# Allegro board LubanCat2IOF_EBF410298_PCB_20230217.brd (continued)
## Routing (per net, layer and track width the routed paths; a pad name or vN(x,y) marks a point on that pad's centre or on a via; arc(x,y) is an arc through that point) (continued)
SATA0TXN: length 3.1
  BOTTOM w0.114: C61.2 122.26,9.97 arc(122.14,9.79) 122.1,9.57 122.1,8.2 arc(122.14,7.98) 122.26,7.8 J34.3
SATA0TXP: length 3.1
  BOTTOM w0.114: C60.2 121.69,10.02 arc(121.81,9.83) 121.85,9.61 121.85,8.2 arc(121.81,7.98) 121.69,7.8 J34.2
SATA_5V: length 12.8
  TOP w0.305: C206.2 R201.2 118.62,18.36 119.23,17.75 v1(124.33,17.75)
  BOTTOM w0.305: v1(124.33,21.89) C208.1 123.44,21.86
  BOTTOM w0.508: J1.1 122.5,16 ; J1.1 121.6,15.1 ; J1.1 121.6,16.9 ; J1.1 120.7,16
  vias: v1(124.33,20.89) v1(124.33,19.89) v1(125.33,21.89) v1(125.33,20.89) v1(125.33,19.89)
SATA_12V: length 4.8
  TOP w0.305: C59.1 v1(135.76,16.3)
  BOTTOM w0.508: J1.4 129.22,16.9 ; J1.4 128.32,16 ; J1.4 130.12,16 ; J1.4 129.22,15.1
  vias: v1(135.76,15.3) v1(136.76,16.3) v1(136.76,15.3)
SATA_PWR_EN: length 143
  TOP w0.173: v1(132.68,6.27) 131.78,7.17 131.78,18.57 131.43,18.92 122.11,18.92 v1(121.41,19.61) R209.2 ; J38.119 v1(44.1,31.92)
  BOTTOM w0.173: v1(44.1,31.92) 106.65,31.92 113.54,25.04 115.37,25.04 115.77,24.63 115.77,20.32 116.18,19.91 121.12,19.91 v1(121.41,19.61) ; R206.1 134.87,6.9 133.32,6.9 v1(132.68,6.27)
SDMMC0_CLK: length 135.7
  TOP w0.173: J38.95 v1(38.1,34)
  BOTTOM w0.173: v1(38.1,34) 108.98,34 110.19,32.78 117.04,32.78 117.29,32.53 117.29,31.69 117.46,31.52 117.88,31.52 118.14,31.77 118.14,32.46 118.39,32.71 118.75,32.71 119,32.46 119,31.77 119.25,31.52 128.78,31.52 135.1,25.19 138.62,25.19 R54.1
SDMMC0_CMD: length 136.9
  TOP w0.173: J38.97 38.6,33.93 v1(39.59,32.93)
  BOTTOM w0.173: v1(39.59,32.93) 40.14,33.48 108.3,33.48 109.6,32.18 114.38,32.18 114.64,31.93 114.64,31.21 114.89,30.96 115.25,30.96 115.51,31.21 115.51,31.87 115.76,32.13 116.12,32.13 116.37,31.87 116.37,31.21 116.62,30.96 128.6,30.96 136.03,23.54 136.03,22.9 136.51,22.41 R53.1
SDMMC0_D0: length 136.9
  TOP w0.173: J38.99 39.1,35.01 v1(39.59,34.51)
  BOTTOM w0.173: R57.1 134.32,26.81 129.08,32.05 125.28,32.05 125.03,32.3 125.03,32.97 124.78,33.22 124.42,33.22 124.17,32.97 124.17,32.3 123.92,32.05 123.58,32.05 123.33,32.3 123.33,33.05 123.08,33.3 122.72,33.3 122.47,33.05 122.47,32.3 122.21,32.05 121.85,32.05 121.6,32.3 121.6,33.05 121.35,33.3 120.99,33.3 120.74,33.05 120.74,32.3 120.49,32.05 120.13,32.05 119.87,32.3 119.87,33.05 119.62,33.3 110.77,33.3 109.56,34.51 v1(39.59,34.51)
SDMMC0_D1: length 135.8
  TOP w0.173: J38.105 40.6,35.77 v1(40.64,35.73)
  BOTTOM w0.173: v1(40.64,35.73) 109.07,35.73 110.99,33.82 125.6,33.82 125.85,33.57 125.85,32.86 126.11,32.61 126.41,32.61 126.66,32.86 126.66,33.5 126.91,33.75 127.27,33.75 127.52,33.5 127.52,32.86 127.78,32.61 129.44,32.61 134.13,27.92 135.36,27.92 135.61,28.17 135.61,29.26 135.87,29.51 136.23,29.51 136.48,29.26 136.48,28.17 136.73,27.92 137.09,27.92 137.34,28.17 137.34,29.26 137.6,29.51 137.95,29.51 138.21,29.26 138.21,28.17 138.46,27.92 R60.1
SDMMC0_D2: length 136.8
  TOP w0.173: J38.93 37.6,33.43 v1(38.1,32.93)
  BOTTOM w0.173: R51.1 136.7,20.22 134.87,22.04 134.87,23.22 128.08,30.02 109.88,30.02 107.46,32.44 38.59,32.44 v1(38.1,32.93)
SDMMC0_D3: length 136.9
  TOP w0.173: v1(40.64,32.94) 40.1,33.48 J38.103
  BOTTOM w0.173: v1(40.64,32.94) 40.66,32.96 107.78,32.96 110.26,30.48 110.87,30.48 111.12,30.73 111.12,31.34 111.37,31.59 111.73,31.59 111.99,31.34 111.99,30.73 112.24,30.48 112.6,30.48 112.85,30.73 112.85,31.34 113.1,31.59 113.46,31.59 113.71,31.34 113.71,30.73 113.97,30.48 128.35,30.48 135.51,23.32 135.51,22.45 136.64,21.32 R52.1
SDMMC0_DET: length 128.9
  TOP w0.173: J38.101 39.6,37.14 v1(39.59,37.13)
  BOTTOM w0.173: R61.1 139.2,29.99 138.81,30.37 132.61,30.37 128.65,34.34 111.82,34.34 109.15,37 39.72,37 v1(39.59,37.13)
SIM_CLK0: length 39.4
  TOP w0.173: J35.12 v1(124.3,65.68)
  ART03 w0.16: v1(136.02,39.8) 135.38,40.43 135.38,51.99 134.75,52.62 128.27,52.62 127.64,53.26 127.64,62.55 127.31,62.87 125.01,62.87 124.79,63.09 124.79,65.19 v1(124.3,65.68)
  BOTTOM w0.173: R20.1 v1(136.02,39.8)
SIM_DATA0: length 44.2
  TOP w0.173: J35.10 125.1,66.88 v1(125.3,66.68)
  ART03 w0.16: v1(138.52,36.24) 138.01,36.75 137.04,36.75 136.5,37.29 136.5,52.77 136.02,53.26 128.78,53.26 128.14,53.89 128.14,63.29 127.89,63.55 126.11,63.55 125.79,63.87 125.79,66.19 v1(125.3,66.68)
  BOTTOM w0.173: R21.1 v1(138.52,36.24)
SIM_RST0: length 43.4
  TOP w0.173: J35.14 123.5,66.85 123.33,66.68 v1(122.86,66.68)
  ART03 w0.16: v1(122.86,66.68) 123.44,66.09 123.44,62.53 123.7,62.28 126.68,62.28 127,61.96 127,52.62 127.64,51.99 133.99,51.99 134.75,51.23 134.75,38.53 v1(136.02,37.26)
  BOTTOM w0.173: R19.1 v1(136.02,37.26)
SIM_VDD: length 47.7
  TOP w0.305: J35.8 125.9,67.08 v1(126.3,66.68)
  ART03 w0.305: v1(126.3,66.68) 128.91,64.07 128.91,54.63 129.51,54.02 136.4,54.02 137.62,52.8 137.62,40.92 138.23,40.32 v1(140.2,40.32) 140.2,37.87 139.59,37.26 v1(138.52,37.26)
  BOTTOM w0.305: R18.1 v1(138.52,37.26) ; U14.1 140.2,40.31 v1(140.2,40.32) U15.6
SPKN_OUT: length 18.5
  TOP w0.254: J38.30 21.85,74.39 22.29,74.82 34.18,74.82 34.47,74.54 34.47,74.02 v1(34.16,73.72)
  BOTTOM w0.254: R218.1 v1(34.16,73.72)
SPKP_OUT: length 20
  TOP w0.254: J38.28 21.35,74.6 21.99,75.23 34.35,75.23 34.87,74.71 34.87,74.02 v1(35.18,73.72)
  BOTTOM w0.254: R217.1 v1(35.18,73.72)
U7_RX: length 7.6
  TOP w0.173: J9.3 94.25,7.12 93.9,6.78 J13.5
U7_TX: length 9.2
  TOP w0.173: J13.6 89.08,10 95.9,10 96.25,9.66 J9.2
U9_RX: length 7.5
  TOP w0.173: J14.5 93.9,12.75 94.25,13.09 J12.3
U9_TX: length 8.6
  TOP w0.173: 88.39,15.29 88.95,15.85 95.02,15.85 J12.2
UART2_RX: length 13.2
  TOP w0.173: U12.2 2.42,21.68 2.59,21.51 4.4,21.51 4.57,21.34 4.57,17.62 4.74,17.45 v1(6.6,17.45)
  BOTTOM w0.173: R36.2 v1(6.6,17.45)
UART2_RX_M0_DEBUG: length 101.8
  TOP w0.173: J38.193 64.1,58.41 v1(63.6,57.91) ; U12.4 v1(1.77,23.04)
  ART03 w0.16: v1(63.6,57.91) 63.09,58.42 48.59,58.42 47.57,57.4 36.6,57.4 v1(36.1,56.91)
  BOTTOM w0.173: v1(1.77,23.04) 12.45,23.04 12.93,23.52 12.93,35.47 14.69,37.23 22.96,37.23 23.67,37.95 23.67,40.9 22.56,42.02 22.56,55.87 23.59,56.91 v1(36.1,56.91)
UART2_TX: length 5.1
  TOP w0.173: U4.4 5.96,20.76 v1(6.6,20.11)
  BOTTOM w0.173: R23.2 v1(6.6,20.11)
UART2_TX_M0_DEBUG: length 91.5
  TOP w0.173: J38.191 v1(63.6,60.91) ; U4.2 6.61,27.57 v1(7.26,28.22)
  ART03 w0.16: v1(63.6,60.91) 64.14,60.37 64.14,59.73 63.81,59.41 47.73,59.41 46.74,58.42 36.61,58.42 v1(36.1,57.91)
  BOTTOM w0.173: v1(7.26,28.22) 11.94,28.22 12.29,28.57 12.29,35.73 14.43,37.87 22.69,37.87 23.04,38.21 23.04,40.64 21.92,41.75 21.92,56.13 23.7,57.91 v1(36.1,57.91)
UART3_RX_M1: length 82.1
  TOP w0.173: v1(46.1,56.91) 46.1,27.18 46.79,26.49 53.63,26.49 53.98,26.14 U8.1 ; J38.271 v1(83.6,63.93)
  BOTTOM w0.173: v1(46.1,56.91) 46.57,56.43 66.02,56.43 72.11,62.53 82.2,62.53 v1(83.6,63.93)
UART3_TX_M1: length 70
  TOP w0.173: U8.4 v1(50.16,25.95) ; v1(83.59,53.95) 83.59,54 83.1,54.49 J38.269
  ART03 w0.16: v1(50.16,25.95) 50.83,25.29 75.95,25.29 76.94,26.28 76.94,50.47 78.16,51.69 79.45,51.69 79.91,52.14 81.79,52.14 v1(83.59,53.95)
UART4_RX_M1: length 75.3
  TOP w0.173: v1(46.12,57.89) 46.1,57.89 46.1,57.91 45.61,57.41 45.61,26.8 46.35,26.06 U13.1 ; J38.267 v1(82.6,63.93)
  BOTTOM w0.173: v1(82.6,63.93) 81.63,62.96 71.93,62.96 65.91,56.94 58.62,56.94 57.86,57.7 46.3,57.7 v1(46.12,57.89)
UART4_TX_M1: length 75.7
  TOP w0.173: U13.4 v1(42.55,25.95) ; J38.265 82.1,54.44 v1(82.59,53.95)
  ART03 w0.16: v1(42.55,25.95) 43.13,26.54 75.83,26.54 76.38,27.09 76.38,50.54 79.78,53.95 v1(82.59,53.95)
UART7_RX: length 18.1
  TOP w0.173: J13.3 84.38,8.25 84.38,17.36 D9.1 83.33,19.71 83.33,22.39 R50.2
UART7_RX_M1: length 72.8
  TOP w0.173: J38.283 86.6,58.63 88.74,56.48 99.65,56.48 101.35,54.79 v1(101.35,40.5) ; R50.1 v1(82.68,24.82)
  ART03 w0.16: v1(101.35,40.5) 102.06,39.78 102.06,31.9 101.55,31.39 88.5,31.39 88.34,31.23 88.34,23.9 87.66,23.21 83.01,23.21 82.68,23.54 v1(82.68,24.82)
UART7_TX: length 15
  TOP w0.173: J13.4 84.86,10.31 84.86,18.4 D8.1 84.86,19.72 84.86,22.38 R49.2
UART7_TX_M1: length 68.3
  TOP w0.173: R49.1 v1(84.2,24.82) ; v1(101.35,39.5) 100.84,40 100.84,54.59 99.32,56.1 88.41,56.1 86.1,58.42 J38.281
  ART03 w0.16: v1(84.2,24.82) 84.2,32.59 84.52,32.91 99.12,32.91 99.44,33.23 99.44,39.54 99.88,39.98 100.86,39.98 v1(101.35,39.5)
UART9_RX: length 11.5
  TOP w0.173: R44.2 88.04,22.25 88.04,19.85 D7.1 87.25,14.14 J14.3
UART9_RX_M1: length 72.1
  TOP w0.173: J38.279 85.6,58.01 87.91,55.7 98.93,55.7 100.35,54.29 v1(100.35,40.5) ; R44.1 v1(87.25,24.82)
  ART03 w0.16: v1(100.35,40.5) 98.92,40.5 98.6,40.18 98.6,33.85 98.27,33.52 83.87,33.52 83.47,33.12 83.47,24.2 83.69,23.97 86.41,23.97 v1(87.25,24.82)
UART9_TX: length 8.3
  TOP w0.173: 85.85,15.29 85.72,15.41 D6.1 86.38,19.71 86.38,22.39 R43.2
UART9_TX_M1: length 65.5
  TOP w0.173: R43.1 v1(85.72,24.82) ; v1(100.35,39.5) 99.69,40.15 99.69,53.74 98.96,54.48 87.7,54.48 87.35,54.82 87.35,55.57 85.1,57.82 J38.277
  ART03 w0.16: v1(100.35,39.5) 100.35,32.52 100.03,32.2 86.2,32.2 85.72,31.73 v1(85.72,24.82)
USB2_HOST2_DM: length 44.6
  TOP w0.132: R152.2 v1(126.75,78.63) ; J38.304 92.35,71.43 arc(92.34,71.5) 92.29,71.56 92.28,71.58 arc(92.23,71.64) 92.22,71.72 92.22,71.88 arc(92.24,72) 92.31,72.1 92.59,72.38 arc(92.73,72.47) 92.89,72.5 93.45,72.5 arc(93.56,72.46) 93.6,72.36 arc(93.64,72.25) 93.75,72.21 93.98,72.21 arc(94.09,72.25) 94.13,72.36 arc(94.17,72.46) 94.28,72.5 94.51,72.5 arc(94.61,72.46) 94.66,72.36 arc(94.7,72.25) 94.81,72.21 95.04,72.21 arc(95.14,72.25) 95.19,72.36 arc(95.23,72.46) 95.33,72.5 95.57,72.5 arc(95.67,72.46) 95.71,72.36 arc(95.76,72.25) 95.86,72.21 96.09,72.21 arc(96.2,72.25) 96.24,72.36 arc(96.29,72.46) 96.39,72.5 96.62,72.5 arc(96.73,72.46) 96.77,72.36 arc(96.81,72.25) 96.92,72.21 97.15,72.21 arc(97.26,72.25) 97.3,72.36 arc(97.34,72.46) 97.45,72.5 98.24,72.5 arc(98.5,72.55) 98.71,72.7 98.91,72.9 arc(99.05,72.99) 99.21,73.02 101.43,73.02 arc(101.61,72.94) 101.69,72.75 101.69,72.59 arc(101.65,72.4) 101.55,72.23 v1(101.38,72.07)
  BOTTOM w0.132: v1(101.38,72.07) 101.65,72.34 arc(101.68,72.38) 101.69,72.44 101.69,72.57 arc(102.94,75.57) 105.94,76.82 126.05,76.82 arc(126.82,77.13) 127.13,77.9 127.13,77.98 arc(127.09,78.23) 126.95,78.43 v1(126.75,78.63)
USB2_HOST2_DP: length 44
  TOP w0.132: v1(102.24,72.07) 102.08,72.23 arc(101.97,72.4) 101.93,72.59 101.93,72.75 arc(101.78,73.11) 101.43,73.26 99.21,73.26 arc(98.95,73.21) 98.74,73.06 98.54,72.87 arc(98.41,72.78) 98.24,72.74 92.89,72.74 arc(92.64,72.69) 92.42,72.55 92.14,72.27 arc(92.02,72.09) 91.98,71.88 91.98,71.72 arc(91.97,71.64) 91.92,71.58 91.91,71.56 arc(91.86,71.5) 91.85,71.43 J38.302 ; R153.2 v1(127.76,78.63)
  BOTTOM w0.132: v1(102.24,72.07) 101.97,72.34 arc(101.94,72.38) 101.93,72.44 101.93,72.57 arc(103.1,75.4) 105.94,76.58 126.05,76.58 arc(126.99,76.96) 127.37,77.9 127.37,77.98 arc(127.42,78.23) 127.56,78.43 v1(127.76,78.63)
USB2_HOST3_DM: length 40.3
  TOP w0.132: J38.298 90.85,71.43 arc(90.84,71.5) 90.79,71.56 90.78,71.58 arc(90.73,71.64) 90.72,71.72 90.72,72.64 arc(91,73.3) 91.66,73.58 97.73,73.58 arc(97.98,73.63) 98.19,73.77 99.87,75.45 arc(100.01,75.66) 100.06,75.91 100.06,79.86 arc(100.01,80.12) 99.87,80.33 98.04,82.16 arc(97.95,82.29) 97.92,82.45 97.92,83.37 arc(97.95,83.44) 98.02,83.47 arc(98.09,83.5) 98.12,83.57 98.12,83.9 arc(98.09,83.97) 98.02,84 arc(97.95,84.03) 97.92,84.1 97.92,84.43 arc(97.95,84.5) 98.02,84.53 arc(98.09,84.56) 98.12,84.63 98.12,84.95 arc(98.09,85.03) 98.02,85.06 arc(97.95,85.09) 97.92,85.16 97.92,92.24 arc(97.95,92.43) 98.06,92.59 v1(98.23,92.76)
  BOTTOM w0.132: v1(98.23,92.76) 98.06,92.92 arc(97.95,93.08) 97.92,93.27 97.92,93.34 arc(97.95,93.51) 98.04,93.64 98.32,93.92 arc(98.45,94.01) 98.62,94.04 104.73,94.04 arc(104.8,94.03) 104.87,93.99 104.88,93.97 arc(104.95,93.93) 105.02,93.91 U28.14
USB2_HOST3_DP: length 40.2
  TOP w0.132: v1(97.37,92.76) 97.53,92.59 arc(97.64,92.43) 97.68,92.24 97.68,82.45 arc(97.73,82.2) 97.87,81.99 99.7,80.16 arc(99.79,80.02) 99.82,79.86 99.82,75.91 arc(99.79,75.75) 99.7,75.62 98.03,73.94 arc(97.89,73.85) 97.73,73.82 91.66,73.82 arc(90.83,73.47) 90.48,72.64 90.48,71.72 arc(90.47,71.64) 90.42,71.58 90.41,71.56 arc(90.36,71.5) 90.35,71.43 J38.296
  BOTTOM w0.132: U28.15 105.02,94.41 arc(104.95,94.4) 104.88,94.36 104.87,94.34 arc(104.8,94.3) 104.73,94.28 98.62,94.28 arc(98.36,94.23) 98.15,94.09 97.87,93.81 arc(97.73,93.6) 97.68,93.34 97.68,93.27 arc(97.64,93.08) 97.53,92.92 v1(97.37,92.76)
USB3_HOST1_DM: length 97.6
  TOP w0.132: v1(46.03,73.42) 45.87,73.25 arc(45.76,73.09) 45.72,72.9 45.72,71.72 arc(45.73,71.64) 45.78,71.58 45.79,71.56 arc(45.84,71.5) 45.85,71.43 J38.126 ; R148.2 v1(124.71,78.63)
  BOTTOM w0.132: v1(124.71,78.63) 124.92,78.43 arc(125.05,78.23) 125.1,77.98 arc(125,77.74) 124.76,77.64 124.36,77.64 arc(124.29,77.67) 124.26,77.75 arc(124.23,77.82) 124.16,77.85 123.84,77.85 arc(123.76,77.82) 123.73,77.75 arc(123.7,77.67) 123.63,77.64 105.08,77.64 arc(103.06,77.24) 101.33,76.09 100.39,75.15 arc(99.08,74.27) 97.53,73.96 73.48,73.96 arc(72.44,73.75) 71.56,73.17 68.82,70.42 arc(68.67,70.2) 68.62,69.95 68.62,69.74 arc(68.5,69.12) 68.15,68.6 65,65.45 arc(63.66,64.56) 62.08,64.24 49.74,64.24 arc(46.9,65.42) 45.72,68.27 45.72,73.05 arc(45.73,73.1) 45.76,73.14 v1(46.03,73.42)
USB3_HOST1_DP: length 98.1
  TOP w0.132: J38.124 45.35,71.43 arc(45.36,71.5) 45.41,71.56 45.42,71.58 arc(45.47,71.64) 45.48,71.72 45.48,72.9 arc(45.44,73.09) 45.33,73.25 v1(45.17,73.42) ; R149.2 v1(125.73,78.63)
  BOTTOM w0.132: v1(125.73,78.63) 125.53,78.43 arc(125.39,78.23) 125.34,77.98 arc(125.17,77.57) 124.76,77.41 105.08,77.41 arc(103.15,77.02) 101.5,75.92 100.56,74.98 arc(99.17,74.05) 97.53,73.72 73.48,73.72 arc(72.53,73.53) 71.73,73 68.99,70.25 arc(68.89,70.11) 68.86,69.95 68.86,69.74 arc(68.72,69.03) 68.32,68.43 65.17,65.29 arc(63.75,64.34) 62.08,64 49.74,64 arc(46.73,65.25) 45.48,68.27 45.48,73.05 arc(45.47,73.1) 45.44,73.14 v1(45.17,73.42)
USB3_HOST1_SSRXN: length 96.3
  TOP w0.132: J38.130 46.85,71.43 arc(46.86,71.5) 46.91,71.56 46.92,71.58 arc(46.97,71.64) 46.98,71.72 46.98,72.53 arc(46.96,72.61) 46.92,72.68 46.85,72.75 arc(46.75,72.9) 46.72,73.07 46.72,74.24 arc(46.68,74.43) 46.57,74.59 v1(46.41,74.76) ; R150.2 v1(122.68,78.63)
  BOTTOM w0.132: v1(46.41,74.76) 46.68,74.48 arc(46.83,74.27) 46.88,74.01 46.88,71.63 arc(46.85,71.56) 46.78,71.53 arc(46.71,71.51) 46.69,71.44 46.69,71.1 arc(46.71,71.03) 46.78,71.01 arc(46.85,70.98) 46.88,70.91 46.88,70.57 arc(46.85,70.51) 46.78,70.48 arc(46.71,70.45) 46.69,70.38 46.69,70.05 arc(46.71,69.98) 46.78,69.95 arc(46.85,69.92) 46.88,69.85 46.88,68.47 arc(47.9,66.01) 50.36,64.99 61.51,64.99 arc(63.11,65.31) 64.47,66.22 67.34,69.08 arc(67.64,69.53) 67.74,70.07 67.74,70.35 arc(67.85,70.89) 68.15,71.35 71.62,74.82 arc(71.99,75.07) 72.44,75.15 93.53,75.15 arc(93.78,75.21) 94,75.35 94.89,76.24 arc(95.02,76.33) 95.19,76.36 96.6,76.36 arc(96.85,76.41) 97.07,76.56 97.94,77.43 arc(98.08,77.53) 98.24,77.56 99.31,77.56 arc(99.56,77.61) 99.78,77.75 100.32,78.3 arc(100.46,78.39) 100.62,78.42 120.48,78.42 arc(120.73,78.47) 120.94,78.61 121.05,78.72 arc(121.26,78.86) 121.52,78.91 122.22,78.91 arc(122.39,78.88) 122.53,78.78 v1(122.68,78.63)
USB3_HOST1_SSRXP: length 96.5
  TOP w0.132: v1(47.27,74.76) 47.1,74.59 arc(46.99,74.43) 46.96,74.24 46.96,73.07 arc(46.97,72.99) 47.02,72.92 47.09,72.85 arc(47.19,72.7) 47.22,72.53 47.22,71.72 arc(47.23,71.64) 47.28,71.58 47.29,71.56 arc(47.34,71.5) 47.35,71.43 J38.132 ; R151.2 v1(123.7,78.63)
  BOTTOM w0.132: v1(123.7,78.63) 123.57,78.63 arc(123.48,78.65) 123.4,78.71 123.13,78.97 arc(122.92,79.12) 122.66,79.17 121.43,79.17 arc(121.18,79.12) 120.96,78.97 120.77,78.78 arc(120.64,78.69) 120.48,78.66 100.62,78.66 arc(100.37,78.61) 100.15,78.47 99.61,77.92 arc(99.47,77.83) 99.31,77.8 98.24,77.8 arc(97.99,77.75) 97.77,77.6 96.9,76.73 arc(96.76,76.63) 96.6,76.6 95.19,76.6 arc(94.93,76.55) 94.72,76.41 93.83,75.52 arc(93.69,75.43) 93.53,75.39 72.44,75.39 arc(71.9,75.29) 71.45,74.98 67.99,71.52 arc(67.63,70.99) 67.5,70.35 67.5,70.07 arc(67.42,69.63) 67.17,69.25 64.31,66.39 arc(63.02,65.53) 61.51,65.23 50.36,65.23 arc(48.07,66.18) 47.12,68.47 47.12,74.5 arc(47.14,74.6) 47.19,74.69 v1(47.27,74.76)
USB3_HOST1_SSTXN: length 99.7
  TOP w0.132: C142.2 v1(128.78,78.63) ; J38.134 47.85,71.43 arc(47.86,71.5) 47.91,71.56 47.92,71.58 arc(47.97,71.64) 47.98,71.72 47.98,72.9 arc(47.94,73.09) 47.83,73.25 v1(47.67,73.42)
  BOTTOM w0.132: v1(47.67,73.42) 47.88,73.21 arc(48.02,72.99) 48.07,72.74 48.07,68.82 arc(48.83,66.99) 50.66,66.23 62,66.23 arc(62.61,66.35) 63.13,66.7 65.1,68.67 arc(65.7,69.57) 65.91,70.63 65.91,71.14 arc(65.96,71.38) 66.09,71.58 69.67,75.16 arc(71.11,76.11) 72.8,76.45 92.59,76.45 arc(92.84,76.5) 93.06,76.64 95.12,78.7 arc(95.25,78.8) 95.41,78.83 97.17,78.83 arc(97.36,78.87) 97.52,78.97 98.26,79.72 arc(98.46,79.85) 98.69,79.89 113.42,79.89 arc(113.63,79.85) 113.81,79.73 113.89,79.65 arc(114.08,79.52) 114.31,79.48 119.42,79.48 arc(119.67,79.53) 119.89,79.67 120.42,80.2 arc(120.55,80.29) 120.72,80.33 128.74,80.33 arc(129.04,80.2) 129.17,79.9 129.17,79.08 arc(129.16,79.03) 129.13,78.98 v1(128.78,78.63)
USB3_HOST1_SSTXP: length 99.6
  TOP w0.132: v1(48.53,73.42) 48.37,73.25 arc(48.26,73.09) 48.22,72.9 48.22,71.72 arc(48.23,71.64) 48.28,71.58 48.29,71.56 arc(48.34,71.5) 48.35,71.43 J38.136 ; C143.2 v1(129.79,78.63)
  BOTTOM w0.132: v1(48.53,73.42) 48.41,73.3 arc(48.34,73.19) 48.31,73.05 48.31,68.82 arc(49,67.16) 50.66,66.47 62,66.47 arc(62.52,66.57) 62.96,66.87 64.94,68.84 arc(65.48,69.66) 65.67,70.63 65.67,71.14 arc(65.74,71.47) 65.92,71.74 69.51,75.33 arc(71.02,76.33) 72.8,76.69 92.59,76.69 arc(92.75,76.72) 92.89,76.81 94.95,78.87 arc(95.16,79.02) 95.41,79.07 97.17,79.07 arc(97.27,79.09) 97.35,79.14 98.09,79.88 arc(98.37,80.07) 98.69,80.13 113.42,80.13 arc(113.72,80.07) 113.98,79.9 114.06,79.82 arc(114.18,79.74) 114.31,79.72 119.42,79.72 arc(119.58,79.75) 119.72,79.84 120.25,80.37 arc(120.46,80.51) 120.72,80.56 128.74,80.56 arc(129.21,80.37) 129.41,79.9 129.41,79.08 arc(129.42,79.03) 129.44,78.98 v1(129.79,78.63)
USB3_OTG0_DM: length 41.9
  TOP w0.132: 27.44,90.15 27.31,90.02 25.06,90.02 24.42,90.66 24.42,91.74 24.55,91.87 J36.B7 24.55,94.88 24.39,95.03 23.74,95.03 23.55,94.85 J36.A7 ; 27.44,90.15 D26.1 ; 27.44,90.15 27.63,89.96 29.13,89.96 29.97,89.12 29.97,82.95 31.04,81.89 39.37,81.89 40.22,81.04 40.22,71.64 40.35,71.51 J38.104
USB3_OTG0_DP: length 41.9
  TOP w0.132: 27.44,89.59 27.57,89.72 29.03,89.72 29.73,89.03 29.73,82.85 30.94,81.65 39.27,81.65 39.98,80.94 39.98,71.64 39.85,71.51 J38.102 ; 27.44,89.59 27.44,89.65 27.31,89.78 24.97,89.78 24.18,90.57 24.18,91.74 24.05,91.87 J36.A6 v1(24.05,94.36) ; 27.44,89.59 D25.1 ; J36.B6 v1(23.05,94.36)
  BOTTOM w0.132: v1(23.05,94.36) 23.05,93.87 23.18,93.74 23.92,93.74 24.05,93.87 v1(24.05,94.36)
USB3_OTG0_ID: length 42.9
  TOP w0.173: J38.118 43.85,71.96 43.5,72.31 41.33,72.31 40.98,72.66 40.98,81.77 39.95,82.8 32,82.8 31.63,83.18 31.63,96.03 31.09,96.57 27.52,96.57 v1(26.76,97.32)
  BOTTOM w0.173: R160.2 v1(26.76,97.32)
USB3_OTG0_VBUSDET: length 40.6
  TOP w0.173: R158.2 v1(23.61,89.25) 23.61,88.98 23.96,88.63 26.63,88.63 26.97,88.29 26.97,80.55 27.32,80.2 v1(39.05,80.2) ; J38.120 44.35,74.3 44,74.65 41.98,74.65 41.63,74.99 41.63,79.84 v1(41.99,80.2)
  BOTTOM w0.173: v1(41.99,80.2) v1(39.05,80.2) ; R158.2 v1(23.61,89.25)
USB20_DM1: length 11
  TOP w0.132: J19.11 126.6,87.18 126.47,87.31 126.47,87.5 arc(126.48,87.57) 126.52,87.63 126.74,87.85 arc(126.88,87.94) 127.04,87.97 127.82,87.97 arc(128.02,87.89) 128.11,87.68 128.11,87.04 arc(128.08,86.89) 127.99,86.76 127.41,86.18 arc(127.26,85.96) 127.21,85.7 127.21,84.41 127.4,84.22 127.4,83.13 arc(127.39,83.06) 127.34,82.99 127.33,82.98 arc(127.28,82.91) 127.27,82.84 U22.10 U22.1 127.27,81.23 arc(127.22,80.97) 127.08,80.76 R152.1
USB20_DP1: length 11.6
  TOP w0.132: R153.1 127.77,80.44 U22.2 U22.9 127.77,82.84 arc(127.76,82.91) 127.71,82.98 127.7,82.99 arc(127.65,83.06) 127.64,83.13 127.64,84.32 127.45,84.51 127.45,85.7 arc(127.49,85.87) 127.58,86.01 128.16,86.59 arc(128.3,86.8) 128.35,87.04 128.35,87.68 arc(128.19,88.05) 127.82,88.21 127.04,88.21 arc(126.78,88.16) 126.57,88.02 126.35,87.8 arc(126.26,87.66) 126.23,87.5 126.23,87.4 arc(126.16,87.24) 126.01,87.18 J19.12
USB20_HOST2_PWR_EN: length 143.5
  TOP w0.173: J38.131 v1(47.1,60.91)
  ART03 w0.16: v1(121.39,98.21) 120.5,97.32 111.96,97.32 111.09,98.19 57.89,98.19 56.52,96.82 50.23,96.82 49.91,96.5 49.91,82.34 49.43,81.86 33.83,81.86 31.14,79.17 31.14,73.5 30.78,73.15 30.78,62.1 31.47,61.41 46.59,61.41 v1(47.1,60.91)
  BOTTOM w0.173: R154.1 v1(121.39,98.21)
USB20_HUB_PWR_EN: length 51.8
  TOP w0.173: v1(120.52,82.44) 121.19,82.44 121.54,82.09 R170.1 ; J38.301 v1(91.1,63.93)
  ART04 w0.16: v1(101.22,63.83) 102.41,63.83 102.95,64.37 102.95,71.08 102.74,71.29 102.74,73.31 103.38,73.95 103.38,81.32 103.67,81.61 119.69,81.61 v1(120.52,82.44)
  BOTTOM w0.173: v1(91.1,63.93) 91.63,64.46 96.65,64.46 97.28,63.83 v1(101.22,63.83)
USB30_DM: length 16.2
  TOP w0.132: J19.2 127.35,90.38 126.75,90.38 arc(126.55,90.46) 126.47,90.66 126.47,91.24 arc(126.36,91.5) 126.09,91.61 124.6,91.61 arc(124.34,91.5) 124.23,91.24 124.23,90.36 arc(124.28,90.1) 124.42,89.89 124.99,89.32 arc(125.08,89.19) 125.11,89.02 125.11,88.73 arc(125.08,88.57) 124.99,88.44 124.53,87.98 arc(124.39,87.76) 124.34,87.51 124.34,87.03 arc(124.39,86.78) 124.53,86.56 125.14,85.96 arc(125.23,85.82) 125.26,85.66 125.26,85.11 arc(125.23,84.94) 125.14,84.81 125.03,84.7 arc(124.89,84.48) 124.84,84.23 124.84,83.13 arc(124.82,83.06) 124.78,82.99 124.76,82.98 arc(124.72,82.91) 124.71,82.84 U23.7 U23.4 124.71,80.44 R148.1
USB30_DP: length 15.6
  TOP w0.132: J19.3 125.35,90.38 125.96,90.38 arc(126.15,90.46) 126.23,90.65 126.23,91.24 arc(126.19,91.34) 126.09,91.37 124.6,91.37 arc(124.51,91.34) 124.47,91.24 124.47,90.36 arc(124.5,90.19) 124.59,90.06 125.16,89.49 arc(125.3,89.28) 125.35,89.02 125.35,88.73 arc(125.3,88.48) 125.16,88.27 124.7,87.81 arc(124.61,87.67) 124.58,87.51 124.58,87.03 arc(124.61,86.87) 124.7,86.73 125.31,86.13 arc(125.45,85.91) 125.5,85.66 125.5,85.11 arc(125.45,84.85) 125.31,84.64 125.2,84.53 arc(125.11,84.39) 125.08,84.23 125.08,83.13 arc(125.09,83.06) 125.13,82.99 125.15,82.98 arc(125.19,82.91) 125.21,82.84 U23.6 U23.5 125.21,81.23 arc(125.26,80.97) 125.4,80.76 R149.1
USB30_HOST1_PWR_EN: length 153.1
  TOP w0.173: J38.129 46.6,60.41 v1(46.1,59.91)
  ART03 w0.16: v1(46.1,59.91) 30.13,59.91 29.36,60.68 29.36,69.59 29.87,70.1 29.87,79.35 33.25,82.72 48.87,82.72 49.38,83.23 49.38,96.91 49.7,97.23 56.24,97.23 57.64,98.63 111.24,98.63 112.12,97.76 120.17,97.76 121.1,98.7 126.51,98.7 v1(126.75,98.93)
  BOTTOM w0.173: R156.1 v1(126.75,98.93)
USB30_RXN: length 9.7
  TOP w0.132: R150.1 123.01,80.76 arc(123.16,80.97) 123.21,81.23 U23.1 U23.10 123.21,82.84 arc(123.22,82.91) 123.26,82.98 123.28,82.99 arc(123.32,83.06) 123.34,83.13 123.34,85.96 arc(123.38,86.16) 123.49,86.34 123.58,86.42 arc(123.64,86.52) 123.66,86.63 123.66,87.4 arc(123.63,87.56) 123.54,87.7 123.42,87.82 arc(123.28,88.03) 123.23,88.29 123.23,88.67 arc(123.17,88.82) 123.02,88.88 J19.5
USB30_RXP: length 9.5
  TOP w0.132: J19.6 123.7,88.88 arc(123.53,88.81) 123.47,88.64 123.47,88.29 arc(123.5,88.13) 123.59,87.99 123.71,87.87 arc(123.85,87.66) 123.9,87.4 123.9,86.63 arc(123.86,86.42) 123.74,86.25 123.66,86.17 arc(123.6,86.07) 123.58,85.96 123.58,83.13 arc(123.59,83.06) 123.63,82.99 123.65,82.98 arc(123.69,82.91) 123.71,82.84 U23.9 U23.2 123.71,80.44 R151.1
USB30_TXN: length 9.7
  TOP w0.132: J19.8 128.41,88.95 128.97,88.95 arc(129.14,88.88) 129.21,88.71 129.21,88.44 arc(129.18,88.31) 129.1,88.19 128.96,88.05 arc(128.82,87.83) 128.77,87.58 128.77,86.81 arc(128.82,86.56) 128.96,86.34 129.06,86.24 arc(129.15,86.1) 129.19,85.94 129.19,84.63 arc(129.17,84.54) 129.12,84.47 129.04,84.39 arc(128.94,84.24) 128.9,84.06 128.9,83.13 arc(128.89,83.06) 128.84,82.99 128.83,82.98 arc(128.78,82.91) 128.77,82.84 U22.7 U22.4 128.77,80.44 C142.1
USB30_TXP: length 9.8
  TOP w0.132: C143.1 129.46,80.76 arc(129.32,80.97) 129.27,81.23 U22.5 U22.6 129.27,82.84 arc(129.26,82.91) 129.21,82.98 129.2,82.99 arc(129.15,83.06) 129.14,83.13 129.14,84.06 arc(129.16,84.14) 129.21,84.22 129.29,84.3 arc(129.39,84.45) 129.43,84.63 129.43,85.94 arc(129.38,86.2) 129.23,86.41 129.13,86.51 arc(129.04,86.65) 129.01,86.81 129.01,87.58 arc(129.04,87.74) 129.13,87.88 129.27,88.02 arc(129.4,88.21) 129.45,88.44 129.45,88.58 arc(129.54,88.79) 129.75,88.88 J19.9
USB_HUB_DM1: length 9.8
  BOTTOM w0.132: J20.2 107.92,86.19 arc(107.77,86.4) 107.72,86.65 107.72,86.79 arc(107.61,87.08) 107.32,87.19 105.91,87.19 arc(105.63,87.31) 105.51,87.59 105.51,88.72 arc(105.54,88.88) 105.64,89.02 106.29,89.67 arc(106.39,89.83) 106.43,90.01 106.43,90.07 arc(106.44,90.14) 106.49,90.2 106.51,90.22 arc(106.55,90.28) 106.56,90.35 U30.9 U30.2 106.56,91.45 arc(106.59,91.61) 106.68,91.74 106.76,91.82 arc(106.9,92.03) 106.95,92.27 U28.11
USB_HUB_DM2: length 4.9
  BOTTOM w0.132: U28.9 107.95,91.87 108.06,91.76 U30.5 U30.6 108.06,90.02 107.93,89.89 107.93,89.4 107.72,89.19 107.72,88.82 108.04,88.5 J20.8
USB_HUB_DM3: length 31.6
  TOP w0.132: v1(111.56,73.37) 111.2,73.73 arc(111.16,73.79) 111.15,73.86 111.15,73.95 110.7,74.4 arc(110.48,74.55) 110.23,74.6 105.29,74.6 arc(105.13,74.63) 104.99,74.72 104.55,75.16 arc(104.47,75.28) 104.44,75.41 104.44,82.21 arc(104.48,82.4) 104.59,82.56 v1(104.76,82.72)
  BOTTOM w0.132: R64.2 v1(111.56,73.37) ; v1(104.76,82.72) 104.59,82.89 arc(104.48,83.05) 104.44,83.24 104.44,83.41 arc(104.54,83.64) 104.78,83.74 108.95,83.74 arc(109.2,83.79) 109.41,83.93 109.76,84.28 arc(109.91,84.5) 109.96,84.75 109.96,89.79 arc(109.91,90.04) 109.76,90.26 108.94,91.08 arc(108.85,91.22) 108.82,91.38 108.82,91.7 arc(108.83,91.77) 108.87,91.83 108.89,91.85 arc(108.93,91.91) 108.95,91.99 U28.7
USB_HUB_DP1: length 9.8
  BOTTOM w0.132: U28.12 106.45,92.3 arc(106.4,92.08) 106.28,91.89 106.2,91.82 arc(106.1,91.66) 106.06,91.48 U30.1 U30.10 106.06,90.35 arc(106.07,90.28) 106.11,90.22 106.14,90.2 arc(106.18,90.14) 106.19,90.07 106.19,90.01 arc(106.17,89.92) 106.12,89.84 105.47,89.19 arc(105.32,88.97) 105.27,88.72 105.27,87.59 arc(105.46,87.14) 105.91,86.96 107.32,86.96 arc(107.44,86.91) 107.48,86.79 107.48,86.65 arc(107.43,86.4) 107.29,86.19 J20.3
USB_HUB_DP2: length 4.9
  BOTTOM w0.132: J20.9 107.16,88.5 107.48,88.82 107.48,89.29 107.69,89.5 107.69,89.89 107.56,90.02 U30.7 U30.4 107.56,91.63 107.45,91.75 U28.10
USB_HUB_DP3: length 31.5
  TOP w0.132: v1(110.62,73.37) 110.85,73.61 arc(110.89,73.67) 110.91,73.75 110.91,73.85 110.53,74.23 arc(110.39,74.33) 110.23,74.36 105.29,74.36 arc(105.03,74.41) 104.82,74.55 104.38,74.99 arc(104.25,75.18) 104.21,75.41 104.21,82.21 arc(104.17,82.4) 104.06,82.56 v1(103.9,82.72)
  BOTTOM w0.132: U28.8 108.45,91.99 arc(108.46,91.91) 108.5,91.85 108.52,91.83 arc(108.56,91.77) 108.58,91.7 108.58,91.38 arc(108.63,91.13) 108.77,90.91 109.59,90.09 arc(109.69,89.95) 109.72,89.79 109.72,84.75 arc(109.69,84.59) 109.59,84.45 109.24,84.1 arc(109.11,84.01) 108.95,83.98 104.78,83.98 arc(104.37,83.81) 104.21,83.41 104.21,83.24 arc(104.17,83.05) 104.06,82.89 v1(103.9,82.72) ; R65.2 v1(110.62,73.37)
USB_OTG_VBUS: length 5.9
  TOP w0.173: J36.A9 21.25,91.73 v1(21.36,91.61) 21.55,91.8 J36.B4 ; J36.B9 26.05,91.73 v1(26.16,91.61) 26.35,91.8 J36.A4
  vias: v1(21.36,90.81) v1(21.36,89.21) v1(22.16,89.21) v1(26.16,90.81)
USB_OTG_VBUS_EN: length 55
  TOP w0.173: J38.127 v1(46.1,60.91)
  ART03 w0.16: v1(46.1,60.91) 45.59,60.4 30.73,60.4 30.38,60.75 v1(30.38,77.26)
  BOTTOM w0.173: v1(30.38,77.26) 30.38,77.78 30.73,78.13 31.67,78.13 32.16,78.61 32.16,80.44 32.94,81.23 32.94,87.42 32.66,87.7 31.28,87.7 31.04,87.95 31.04,90.76 30.69,91.11 28.29,91.11 27.94,90.76 R161.1
N28611: length 6
  TOP w0.173: U5.4 1.9,68.43 1.73,68.61 1.73,70.23 1.91,70.41 R13.1 R11.1 C24.1
N15580021: length 3.3
  TOP w0.173: U18.25 67.11,43.55 R91.2
N15580025: length 3.2
  TOP w0.173: R92.2 66.71,43.13 U18.24
N15580029: length 3.5
  TOP w0.173: U18.23 66.31,43.87 R93.2
N15580033: length 3.8
  TOP w0.173: R94.2 65.91,44.61 U18.22
N15580037: length 4.3
  TOP w0.173: R95.2 69.23,43.71 68.66,43.71 67.91,44.46 U18.27
N15580041: length 3.6
  TOP w0.173: U18.26 67.51,44.29 R96.2
N15582684: length 5.9
  TOP w0.173: R104.2 v1(72.03,44.12) 70.99,45.16 70.99,46.43 70.66,46.76 U18.31
  BOTTOM w0.173: R103.2 72.17,44.25 v1(72.03,44.12)
N15584123: length 9.7
  TOP w0.173: U18.36 71.58,48.76 72.02,49.2 72.02,49.68 72.19,49.86 72.58,49.86 72.78,49.66 ; Y3.3 77.2,49.66 77.03,49.83 72.95,49.83 72.78,49.66 ; 72.78,49.66 C77.1
N15584130: length 8
  TOP w0.173: 72.78,50.33 72.63,50.18 72.05,50.18 71.69,49.82 71.69,49.34 71.52,49.16 U18.37 ; 72.78,50.33 C76.1 ; 72.78,50.33 72.95,50.16 75.53,50.16 75.7,50.33 Y3.1
N15584385: length 8.6
  TOP w0.173: D22.1 59.68,47.14 R184.2 R107.2 C78.1 59.78,49.96 U18.12
N15584944: length 4.3
  TOP w0.173: U18.32 70.85,47.16 71.5,46.51 71.5,45.61 71.98,45.13 R110.1
N15590489: length 4.4
  TOP w0.173: U18.39 70.36,49.96 70.61,50.21 70.61,51.44 70.91,51.74 R100.1
N15599533: length 3.3
  TOP w0.173: R118.2 87.56,43.55 U19.25
N15599537: length 3.2
  TOP w0.173: U19.24 87.16,43.13 R119.2
N15599541: length 3.5
  TOP w0.173: R120.2 86.76,43.87 U19.23
N15599545: length 3.8
  TOP w0.173: R122.2 86.36,44.61 U19.22
N15599549: length 4.3
  TOP w0.173: R123.2 89.68,43.71 89.1,43.71 88.36,44.46 U19.27
N15599553: length 3.6
  TOP w0.173: R124.2 87.96,44.29 U19.26
N15600826: length 6.2
  TOP w0.173: U19.31 91.11,46.76 91.44,46.43 91.44,45.16 v1(91.91,44.69) 92.48,44.12 R132.2
  BOTTOM w0.173: v1(91.91,44.69) 91.97,44.62 R130.2
N15601838: length 8.2
  TOP w0.173: Y4.1 96.4,50.33 96.23,50.16 93.4,50.16 93.23,50.33 ; U19.37 91.96,49.16 92.14,49.34 92.14,49.82 92.5,50.18 93.07,50.18 93.23,50.33 ; C98.1 93.23,50.33
N15601846: length 9.9
  TOP w0.173: U19.36 92.02,48.76 92.46,49.2 92.46,49.68 92.64,49.86 93.03,49.86 93.23,49.66 ; C99.1 93.23,49.66 ; 93.23,49.66 93.4,49.83 97.71,49.83 97.91,49.64 Y4.3
N15602147: length 8.5
  TOP w0.173: D35.1 80.13,46.89 R238.2 R136.2 C101.1 80.25,49.96 U19.12
N15602572: length 4.3
  TOP w0.173: U19.32 91.29,47.16 91.95,46.51 91.95,45.61 92.43,45.13 R139.1
N15603170: length 2.4
  BOTTOM w0.173: C100.1 93.64,79.88 J18.1
N15605512: length 4.4
  TOP w0.173: R121.1 91.36,51.74 91.06,51.44 91.06,50.21 90.81,49.96 U19.39
N15772454: length 3
  TOP w0.173: J26.14 150.33,48.19 150.17,48.36 R208.2
N15774097: length 3.7
  TOP w0.173: J23.14 150,70.93 149.77,71.16 149.77,71.77 149.48,72.06 R204.2
N16795890: length 3.4
  TOP w0.305: U5.5 v1(1.91,67.48)
  BOTTOM w0.305: v1(1.91,67.48) R225.1 R12.1
N17344359: length 10.5
  BOTTOM w1.016: J39.1 8.49,98.76 L2.1 16.61,98.76 J39.5
N17345183: length 6
  TOP w0.173: C14.1 R6.1 R7.1 1.91,42.47 1.73,42.29 1.73,40.67 1.9,40.49 U2.4
N17367006: length 6
  TOP w0.173: U1.4 1.9,54.46 1.73,54.64 1.73,56.26 1.91,56.44 R3.1 R1.1 C2.1
N17371141: length 1.9
  TOP w0.173: LED1.1 v1(137.65,98.39)
  BOTTOM w0.173: R4.2 137.61,98.34 v1(137.65,98.39)
N17385739: length 1.9
  TOP w0.173: LED2.1 v1(142.32,98.39)
  BOTTOM w0.173: R31.2 142.27,98.34 v1(142.32,98.39)
N17407470: length 3.2
  BOTTOM w0.173: J4.1 R51.2
N17407472: length 3.2
  BOTTOM w0.173: J4.7 R57.2
N17407474: length 3.2
  BOTTOM w0.173: J4.5 R54.2
N17407476: length 3.2
  BOTTOM w0.173: J4.3 R53.2
N17407478: length 3.2
  BOTTOM w0.173: R52.2 J4.2
N17407480: length 3.2
  BOTTOM w0.173: R60.2 J4.8
N17407510: length 3.2
  BOTTOM w0.173: J4.9 R61.2
N17408573: length 2.6
  BOTTOM w0.173: C31.1 75.32,82.14 J11.1
N17409833: length 3.3
  TOP w0.173: U7.5 v1(122.81,60.68)
  BOTTOM w0.173: R17.1 R16.2 v1(122.81,60.68)
N17409879: length 5.3
  TOP w0.173: U7.4 121.86,60.73 121.69,60.56 120.43,60.56 120.26,60.73 C32.2 R14.2 R15.1
N17410340: length 10
  BOTTOM w0.173: R19.2 C52.1 138.56,39.04 138.56,40.13 138.73,40.31 139.53,40.31 139.7,40.48 U15.5 139.7,42.68 139.87,42.85 U14.2
N17410342: length 10.5
  BOTTOM w0.173: U14.3 139.45,45.39 139.2,45.14 U15.4 138.62,41.01 138.43,40.81 C51.1 R20.2
N17410344: length 12.9
  BOTTOM w0.173: R21.2 R18.2 C47.1 140.2,38.27 U15.1 144.02,39.66 144.2,39.83 144.2,43.95 144.02,44.12 U14.7
N17411312: length 6.9
  TOP w0.173: v1(128.24,73.57) 128.7,74.03 J35.1
  BOTTOM w0.173: R22.2 128.06,71.54 128.24,71.73 v1(128.24,73.57) R29.2
N17411326: length 4.2
  TOP w0.173: v1(125.48,73.57) 125.48,73.57 126.3,74.39 J35.7
  BOTTOM w0.173: R30.2 v1(125.48,73.57)
N17411361: length 2.7
  TOP w0.173: R62.1 117.9,65.78 J35.20
N17411393: length 2.7
  TOP w0.173: J35.22 117.1,65.83 R63.1
N17411481: length 3.4
  TOP w0.132: J35.38 110.7,69.2 arc(110.74,69.4) 110.86,69.58 110.88,69.6 arc(110.99,69.77) 111.03,69.97 111.03,70.09 arc(110.99,70.28) 110.89,70.45 v1(110.72,70.61)
  BOTTOM w0.132: v1(110.72,70.61) 110.66,70.67 arc(110.63,70.72) 110.62,70.78 R65.1
N17411507: length 3.3
  TOP w0.132: v1(111.58,70.61) 111.42,70.45 arc(111.31,70.28) 111.27,70.09 111.27,69.93 arc(111.3,69.79) 111.38,69.67 111.39,69.65 arc(111.47,69.54) 111.5,69.4 J35.36
  BOTTOM w0.132: v1(111.58,70.61) 111.56,70.64 R64.1
N17438974: length 1.3
  TOP w0.305: D4.2 48.29,16.81 R37.2
N17440531: length 1.3
  TOP w0.305: D5.2 40.67,16.81 R67.2
N17441588: length 5.7
  TOP w0.173: U11.3 v1(67.06,20.36)
  BOTTOM w0.173: C49.1 64.52,20.75 64.92,21.15 66.27,21.15 v1(67.06,20.36)
N17441590: length 2.8
  TOP w0.173: U11.1 v1(64.52,17.32)
  BOTTOM w0.173: C49.2 64.52,17.33 v1(64.52,17.32)
N17441592: length 2.8
  TOP w0.173: U11.5 v1(69.6,17.33)
  BOTTOM w0.173: v1(69.6,17.33) 69.6,17.34 C50.1
N17441594: length 7.3
  TOP w0.173: U11.4 68.32,16.82 68.8,16.33 v1(69.6,16.33)
  BOTTOM w0.173: v1(69.6,16.33) 70.23,16.96 70.23,18.96 C50.2
N17441596: length 2.8
  TOP w0.173: U11.6 v1(70.86,17.33)
  BOTTOM w0.173: C48.1 70.87,17.34 v1(70.86,17.33)
N17441598: length 2.3
  TOP w0.173: U11.2 v1(65.78,20.37)
  BOTTOM w0.173: v1(65.78,20.37) 65.79,20.37 C45.1
N17485809: length 3.4
  TOP w0.173: U20.5 v1(139.34,60.88)
  BOTTOM w0.173: R76.1 R75.1 v1(139.34,60.88)
N17485876: length 5.3
  TOP w0.173: R73.1 C69.1 R74.1 139.21,58.59 139.38,58.76 139.38,59.76 139.21,59.93 U20.4
N17487342: length 6.1
  TOP w0.173: J17.38 145.9,85.6 145.73,85.77 143.23,85.77 v1(142.88,86.13)
  BOTTOM w0.173: R81.1 142.7,86.91 142.88,86.74 v1(142.88,86.13)
N17487441: length 2.5
  TOP w0.173: v1(138.94,86.15) 138.9,86.11 J17.10
  BOTTOM w0.173: v1(138.94,86.15) 138.68,85.9 R80.1
N17494240: length 33.7
  TOP w0.173: 132.92,82.09 L19.1
  TOP w0.508: J19.22 J19.21 132.92,82.09 ; J19.20 J19.19
  BOTTOM w0.508: J19.20 119.78,84.63 120.28,84.12 132.41,84.12 132.92,84.63 J19.21
N17495021: length 3.7
  BOTTOM w0.173: U26.4 128.08,96.89 127.91,96.72 127.24,96.72 R156.2 C147.1
N17495041: length 2
  BOTTOM w0.173: R157.1 128.08,93.7 U26.3
N17495139: length 3.5
  BOTTOM w0.173: C146.1 R154.2 122.51,96.87 123.34,96.87 123.51,97.04 U24.4
N17495165: length 2
  BOTTOM w0.173: U24.3 123.51,93.7 R155.1
N17495663: length 20
  ART03 w0.508: J36.C2 J36.C1
  BOTTOM w0.508: L20.1 19.43,94.17 J36.C4 J36.C2 ; J36.C3 J36.C1
N17495859: length 2.5
  BOTTOM w0.173: D27.3 25.48,95.89 R160.1
N17496265: length 3.5
  BOTTOM w0.173: U25.3 25.8,87.61 25.51,87.9 25.51,88.68 25.79,88.96 R162.1
N17496334: length 4.8
  BOTTOM w0.173: R161.2 C150.1 30.23,88.96 30.4,88.78 30.4,87.78 30.23,87.61 U25.4
N17505436: length 1.6
  BOTTOM w0.173: U28.13 104.02,93.41 R163.1
N17505526: length 1.6
  BOTTOM w0.173: U28.16 104.01,94.91 R164.1
N17505593: length 2.7
  BOTTOM w0.173: U28.18 105.6,96.9 105.42,97.07 R165.1
N17505596: length 5.9
  BOTTOM w0.173: U28.17 104.65,95.41 C153.1 103.45,95.5 101.05,95.5 R166.1
N17506485: length 3.1
  BOTTOM w0.173: R168.1 109.1,97.78 108.93,97.61 107.57,97.61 107.45,97.49 U28.21
N17506866: length 6.8
  BOTTOM w0.173: R169.2 113.5,97.79 111.69,97.79 C158.1 110.74,97.96 110.74,96.08 110.57,95.91 U28.1
N17515649: length 7.2
  BOTTOM w0.173: Y2.1 115.43,96 115.26,95.83 112.5,95.83 C138.1 111.73,95.78 111.46,95.78 110.59,94.91 U28.3
N17515683: length 5.7
  BOTTOM w0.173: Y2.3 113.93,95.33 113.76,95.51 112.48,95.51 C137.1 111.86,95.44 111.6,95.44 110.57,94.41 U28.4
N17516865: length 28.9
  ART03 w0.762: J20.11 J20.12
  BOTTOM w0.762: L21.1 99.97,84.41 J20.5 J20.11 ; J20.12 J20.6
N17517489: length 2.8
  TOP w0.173: R170.2 C163.1 120.47,79.49 U29.4
N17517506: length 2
  TOP w0.173: U29.3 115.13,79.49 114.94,79.29 R171.1
N17532429: length 15.8
  TOP w0.173: R55.2 114.35,22.33 114.35,19.77 D19.1 115.06,10.82 J15.1
N17532431: length 16.5
  TOP w0.173: R56.2 112.78,22.28 112.78,19.82 D13.1 113.54,16.51 114.07,15.97 114.07,11.83 J15.2
N17532433: length 16.2
  TOP w0.173: R58.2 111.25,22.28 111.25,19.82 D12.1 112.01,11.77 J15.3
N17532435: length 16.4
  TOP w0.173: R59.2 109.75,22.31 109.75,19.8 D11.1 110.49,16.53 109.93,15.97 109.93,11.69 J15.4
N17532437: length 16.6
  TOP w0.173: J15.5 108,11.76 108,16.15 108.97,17.12 D10.1 108.25,19.77 108.25,22.33 R71.2
N17536330: length 4.2
  TOP w0.381: U3.2 v1(148.14,98.47)
  BOTTOM w0.381: v1(148.14,98.47) 148.21,98.4 C15.1 C16.1 R66.1
N17536407: length 3.2
  TOP w0.173: U3.3 v1(146.87,98.47)
  BOTTOM w0.173: R34.2 R32.2 146.81,98.42 v1(146.87,98.47)
N17536851: length 7.6
  BOTTOM w0.173: SW3.2 21.63,10.38 D3.2 21.63,12.32 21.07,12.87 C65.1 21.07,14.06 20.9,14.24 18.86,14.24 18.69,14.06 R26.1
N17545096: length 3.4
  TOP w0.173: R174.2 C172.1 U33.4
N17545112: length 2
  TOP w0.173: R175.1 147.39,59.42 U33.3
N17546367: length 3.3
  BOTTOM w0.114: J24.8 150.63,72.98 150.5,72.85 149.13,72.85 149.02,72.97 149.02,73.12 148.91,73.24 R231.2
N17546373: length 3.5
  BOTTOM w0.114: J24.12 150.63,74.98 150.5,74.85 150.15,74.85 149.65,75.35 149.13,75.35 149.02,75.47 149.02,75.62 148.91,75.74 R233.2
N17546399: length 3.3
  BOTTOM w0.114: J24.7 150.63,72.48 150.5,72.61 149.13,72.61 149.02,72.5 149.02,72.34 148.91,72.22 R230.2
N17546411: length 3.5
  BOTTOM w0.114: J24.11 150.63,74.48 150.5,74.61 150.05,74.61 149.55,75.11 149.13,75.11 149.02,75 149.02,74.84 148.91,74.72 R232.2
N17548144: length 3.4
  TOP w0.173: R185.2 C176.1 U36.4
N17548162: length 2.1
  TOP w0.173: U36.3 147.26,70.72 R186.1
N17550903: length 2
  TOP w0.173: U37.3 146.72,16.11 146.91,16.3 R190.1
N17550993: length 3.7
  TOP w0.173: R189.1 C201.1 142.11,16.3 142.31,16.11 U37.4
N17558620: length 2.7
  TOP w0.173: U38.3 v1(101.03,23.6)
  BOTTOM w0.173: R192.1 100.97,23.54 v1(101.03,23.6)
N17558699: length 5
  TOP w0.173: R191.2 C204.1 96.74,24.94 96.39,24.59 96.39,23.95 96.74,23.6 U38.4
N17562506: length 9
  TOP w0.173: R195.2 C189.1 ; C189.1 C192.1 U35.4 ; C189.1 U34.4
N17562520: length 5.1
  TOP w0.173: R196.1 144.78,63.93 144.59,63.74 144.59,62.89 144.76,62.72 U34.3
N17562633: length 5.3
  TOP w0.173: R197.1 144.65,67.99 144.46,67.8 144.46,66.96 144.64,66.78 U35.3
N17563970: length 9.1
  TOP w0.173: U39.4 142.31,40.88 142.11,41.07 C193.1 ; U40.4 C200.1 C193.1 ; C193.1 R200.1
N17564290: length 2.9
  TOP w0.173: U39.3 146.66,40.88 146.84,41.05 146.84,41.91 147.02,42.08 R198.1
N17565184: length 2.3
  TOP w0.173: U40.3 144.77,44.94 144.6,45.11 144.6,45.85 R199.1
N17577061: length 4.7
  TOP w0.173: R209.1 R202.1 119.63,21.16 119.46,21.33 117.65,21.33 117.47,21.5 U41.5
N17577114: length 3.8
  TOP w0.173: R201.1 C206.1 R203.1 116.52,20.67 U41.4
N17577685: length 3.3
  TOP w0.173: Q10.1 134.05,11.93 R205.2 135,10.98 Q14.3
N17577722: length 3.4
  TOP w0.173: Q14.1 134.5,7.38 R207.1 v1(133.68,6.27)
  BOTTOM w0.173: R207.1 v1(133.68,6.27)
N17590789: length 24.6
  TOP w0.203: C215.2 v1(22.77,87.1)
  ART03 w0.203: v1(32.26,92.88) 32,92.88 31.09,91.97 31.09,89.34 29.94,88.18 25.49,88.18 24.73,87.42 23.09,87.42 v1(22.77,87.1)
  BOTTOM w0.203: J25.3 36.61,88.68 J25.4 34.71,93.34 34.5,93.54 33.84,93.54 D34.1 v1(32.26,92.88)
N17590802: length 26.4
  TOP w0.203: C214.2 v1(21.26,87.1)
  ART03 w0.203: v1(21.26,87.1) 22.29,88.13 24.43,88.13 25.2,88.9 29.64,88.9 30.38,89.63 30.38,92.53 v1(32.26,94.41)
  BOTTOM w0.173: 36.71,94.28 J25.2
  BOTTOM w0.203: v1(32.26,94.41) D33.1 33.69,93.9 36.32,93.9 J25.2 ; R211.2 36.71,94.28
N17590849: length 2.8
  BOTTOM w0.173: R210.2 37.45,84.98 J25.1
N17609931: length 2
  BOTTOM w0.203: R214.1 C216.1 R213.2
N17615054: length 3.8
  BOTTOM w0.254: J31.1 34.92,77.77 34.92,76.72 D31.1 35.18,76.28 R217.2
N17615057: length 3.7
  BOTTOM w0.254: J31.2 34.42,77.94 34.42,76.72 D32.1 34.16,76.28 R218.2
N17639389: length 7.6
  TOP w0.173: U21.5 139.49,76.57 C132.1 138.71,75.9 135.35,75.9 135.01,76.24 Y1.1
N17639396: length 2
  TOP w0.173: R144.1 139.44,73.32 U21.10
N17639427: length 7.5
  TOP w0.381: U21.15 148.7,75.92 v1(150.26,77.48)
  BOTTOM w0.305: C135.1 C134.1 ; C134.1 149.97,77.77 v1(150.26,77.48) ; C134.1 R145.1
N17639486: length 4
  TOP w0.114: U21.20 146.55,79.17 arc(146.5,79.16) 146.46,79.14 146.33,79 arc(146.29,78.98) 146.25,78.97 145.89,78.97 arc(145.73,79.03) 145.66,79.2 145.66,80.3 arc(145.7,80.38) 145.78,80.41 145.94,80.41 arc(146.02,80.45) 146.05,80.53 R77.1
N17639523: length 4.4
  TOP w0.114: U21.19 146.55,78.52 arc(146.5,78.53) 146.46,78.56 146.33,78.69 arc(146.29,78.72) 146.25,78.73 145.89,78.73 arc(145.56,78.86) 145.42,79.2 145.42,80.3 arc(145.39,80.38) 145.31,80.41 145.15,80.41 arc(145.07,80.45) 145.03,80.53 R78.1
N17639615: length 7.6
  TOP w0.114: U21.18 146.63,77.87 arc(146.51,77.85) 146.4,77.78 146.39,77.76 arc(146.28,77.69) 146.16,77.67 145.67,77.67 arc(145.59,77.7) 145.55,77.78 arc(145.52,77.86) 145.44,77.9 145.21,77.9 arc(145.13,77.86) 145.09,77.78 arc(145.06,77.7) 144.98,77.67 144,77.67 arc(143.87,77.69) 143.76,77.76 143.47,78.06 arc(143.4,78.16) 143.38,78.29 143.38,80.28 arc(143.41,80.36) 143.49,80.39 143.65,80.39 arc(143.73,80.42) 143.76,80.5 R87.1
N17639617: length 7.7
  TOP w0.114: U21.17 146.63,77.22 arc(146.51,77.25) 146.4,77.32 146.39,77.33 arc(146.28,77.4) 146.16,77.43 144,77.43 arc(143.78,77.47) 143.59,77.59 143.3,77.88 arc(143.18,78.07) 143.14,78.29 143.14,80.28 arc(143.1,80.36) 143.02,80.39 142.86,80.39 arc(142.78,80.42) 142.75,80.5 R111.1
N17639713: length 3.1
  TOP w0.173: Y1.3 138.06,74.72 C133.1 R221.1
N17683065: length 2.6
  TOP w0.305: U1.5 v1(1.8,53.51)
  BOTTOM w0.305: R2.1 v1(1.8,53.51)
N17697748: length 2.2
  TOP w0.173: U21.6 140,75.92 R221.2
N17699685: length 2.2
  BOTTOM w0.173: R28.1 76.29,98.22 J11.11
N17699996: length 2.2
  BOTTOM w0.173: J11.13 65.58,98.21 R27.1
N17700387: length 2.2
  BOTTOM w0.173: R133.1 94.58,96.03 J18.11
N17700720: length 2.2
  BOTTOM w0.173: R131.1 83.86,96.02 J18.13
N17737040: length 3.2
  BOTTOM w0.114: J22.16 150.63,58.78 150.5,58.91 148.82,58.91 R226.2
N17737043: length 3.2
  BOTTOM w0.114: R227.2 148.82,59.15 150.5,59.15 150.63,59.28 J22.17
N17737126: length 11.1
  BOTTOM w0.114: R228.2 148.88,65.15 148.99,65.04 148.99,64.88 149.11,64.77 150.9,64.77 151.22,64.45 151.22,63.62 151.38,63.46 153.07,63.46 153.5,63.03 153.5,60.74 153.17,60.41 152.36,60.41 152.23,60.28 J22.19
N17737138: length 10.3
  BOTTOM w0.114: J22.20 152.23,60.78 152.36,60.65 153.07,60.65 153.26,60.84 153.26,62.93 152.97,63.22 151.28,63.22 150.98,63.52 150.98,64.35 150.8,64.53 149.11,64.53 148.99,64.41 148.99,64.25 148.88,64.14 R229.2
N17802924: length 2.8
  BOTTOM w0.173: Q3.1 30.42,80.26 R9.2 29.46,79.3 Q4.3
N17802940: length 2.4
  BOTTOM w0.173: R10.2 R234.1 29.97,75.23 30.42,75.68 Q4.1
N17802978: length 4.9
  BOTTOM w0.173: 24.77,77.81 J6.1
  BOTTOM w0.508: 24.77,77.81 D20.2 26.24,80.26 R5.2
N17803061: length 2.6
  BOTTOM w0.508: Q3.3 29.38,82.98 R5.1
N17804550: length 2.2
  TOP w0.305: U16.5 v1(3.94,75)
  BOTTOM w0.305: R236.1 v1(3.94,75)
N17804616: length 3.7
  TOP w0.173: C140.1 R235.1 R237.1 2.99,74.27 U16.4
N17822498: length 25.5
  BOTTOM w1.016: C166.1 68.83,96.18 R173.1 68.71,89.19 ; J11.16 67.56,88.05 68.71,89.19 ; 68.71,89.19 69.85,88.05 J11.15
N17836581: length 25.8
  BOTTOM w1.016: J18.15 87.78,88.05 86.92,88.91 ; 86.92,88.91 86.06,88.05 J18.16 ; 86.92,88.91 R183.1 87.04,96.18 C167.1

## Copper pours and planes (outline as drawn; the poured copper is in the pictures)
1V05_PHY0 on TOP: 70.82,40 74.37,40 74.55,40.18 74.55,43.07 74.4,43.23 72.8,43.23 72.8,40.71 72.69,40.61 70.82,40.61
1V05_PHY1 on TOP: 91.26,40 94.82,40 95,40.18 95,43.07 94.84,43.23 93.24,43.23 93.24,40.71 93.14,40.61 91.26,40.61
12V on TOP: 4.7,40.15 7.16,40.15 7.32,40.31 7.32,42.54 7.16,42.69 5.97,42.69 5.84,42.57 5.84,40.97 5.71,40.84 4.7,40.84
12V on TOP: 135.2,11.17 135.2,13.05 135.41,13.25 137.82,13.25 138.02,13.05 138.02,11.25 137.82,11.05 135.33,11.05
12V on TOP: 145.31,31.62 145.31,28.44 149.73,28.44 150.14,28.85 150.14,31.24 149.76,31.62
12V on TOP: 1.4,77.72 1.4,79.96 1.5,80.06 3.78,80.06 3.89,79.96 3.89,79.07 3.81,78.99 3.45,78.99 3.33,78.86 3.33,77.75 3.17,77.59 1.52,77.59
12V on TOP: 4.7,68.09 7.16,68.09 7.32,68.25 7.32,70.48 7.16,70.63 5.97,70.63 5.84,70.51 5.84,68.91 5.71,68.78 4.7,68.78
12V on TOP: 4.7,54.12 7.16,54.12 7.32,54.28 7.32,56.51 7.16,56.66 5.97,56.66 5.84,56.54 5.84,54.94 5.71,54.81 4.7,54.81
12V on TOP: 2.29,83.08 12.75,83.08 12.95,82.88 12.95,79.73 12.8,79.57 9.58,79.57 9.45,79.7 9.45,81.12 9.27,81.3 2.29,81.3
12V on TOP: 116.87,24.3 116.87,25.57 117.14,25.85 117.14,28.37 116.92,28.6 113.49,28.6 113.28,28.39 113.28,26.26 113.46,26.08 115.67,26.08 116.18,25.57 116.18,24.3
12V on BOTTOM: 4.14,40.15 7.14,40.15 7.37,40.38 7.37,46.96 7.65,47.24 11.05,47.24 11.35,47.54 11.35,70.25 10.97,70.63 6.71,70.63 6.32,71.01 6.32,74.01 6.05,74.29 3.58,74.29 3.4,74.47 3.4,79.42 3.53,79.55 3.76,79.55 3.91,79.7 3.91,80.06 4.22,80.36 9.19,80.36 9.4,80.16 9.4,79.78 9.6,79.57 12.83,79.57 13,79.75 13,81.89 12.8,82.09 3.94,82.09 3.61,81.76 1.63,81.76 1.35,81.48 1.35,72.41 1.65,72.11 3.84,72.11 4.14,71.8 4.14,68.2 4.22,68.12 7.9,68.12 8.2,67.81 8.2,57.53 7.75,57.07 4.14,57.07 4.14,54.23 7.72,54.23 8.2,53.74 8.2,50.44 7.7,49.93 4.7,49.93 4.14,49.37
12V on BOTTOM: 113.21,26.29 113.28,26.11 113.46,26.03 117.17,26.03 117.35,26.11 117.42,26.29 117.42,28.37 117.35,28.55 117.17,28.62 113.46,28.62 113.28,28.55 113.21,28.37
12V on ART04: 7.92,42.74 8.33,42.34 8.33,30.81 9.19,29.94 148.69,29.94 148.95,29.69 148.95,26.69 148.69,26.44 139.95,26.44 139.55,26.03 139.55,11.45 139.04,10.94 131.98,10.94 131.47,11.45 131.47,14.04 130.81,14.7 4.22,14.7 3.56,15.36 3.56,19.58 3.2,19.94 1.93,19.94 1.47,20.39 1.47,42.39 1.83,42.74
12V_IN on TOP: 8.64,92.91 2.9,92.91 2.29,92.3 2.29,85.92 8,85.92 8.64,86.56
GND on TOP: 10.21,65.1 10.29,64.92 10.46,64.84 11.73,64.84 11.91,64.92 11.99,65.1 11.99,72.31 11.91,72.49 11.73,72.56 10.46,72.56 10.29,72.49 10.21,72.31
GND on TOP: 23.52,83.08 23.59,82.9 23.77,82.83 25.76,82.83 25.94,82.9 26.01,83.08 26.01,84.73 25.94,84.91 25.76,84.98 23.77,84.98 23.59,84.91 23.52,84.73
GND on TOP: 2,5.5 0.94,5.94 0.5,7 0.5,98 0.94,99.06 2,99.5 17.86,99.5 17.86,97.43 19.51,97.43 19.51,99.5 61.64,99.5 61.64,87.5 96.11,87.5 96.11,99.5 156,99.5 157.06,99.06 157.5,98 157.5,7 157.06,5.94 156,5.5 ; 189 cut-outs
GND on TOP: 5.59,68.07 8,68.07 8.2,67.86 8.2,64.18 8.46,63.93 9.83,63.93 10.19,63.57 10.19,62 6.88,62 6.88,63.83 6.58,64.13 4.9,64.13 4.65,64.39 4.65,67.13
GND on TOP: 129.92,81.73 130,81.55 130.18,81.48 131.55,81.48 131.73,81.55 131.8,81.73 131.8,83.1 131.73,83.28 131.55,83.36 130.18,83.36 130,83.28 129.92,83.1
GND on TOP: 4.52,77.77 4.52,78.84 4.37,78.99 4.37,79.9 4.52,80.06 6.76,80.06 6.88,79.93 6.88,78.74 6.71,78.56 5.36,78.56 5.23,78.43 5.23,77.77
GND on TOP: 5.59,40.13 9.8,40.13 10.19,39.75 10.19,34.06 6.88,34.06 6.88,35.89 6.58,36.19 4.9,36.19 4.65,36.45 4.65,39.19
GND on TOP: 5.59,54.1 9.91,54.1 10.19,53.82 10.19,48.03 6.88,48.03 6.88,49.86 6.58,50.16 4.9,50.16 4.65,50.42 4.65,53.16
GND on BOTTOM: 13.44,95.25 13.51,95.07 13.69,94.99 15.04,94.99 15.22,95.07 15.29,95.25 15.29,97.41 15.22,97.58 15.04,97.66 13.69,97.66 13.51,97.58 13.44,97.41
GND on BOTTOM: 156,99.5 157.06,99.06 157.5,98 157.5,7 157.06,5.94 156,5.5 20.75,5.5 20.75,56.16 23.8,59.2 29.44,59.2 29.77,59.53 29.77,70.28 31.19,71.7 41.22,71.7 45.24,75.71 47.37,75.71 48.08,76.42 48.08,99.36 48.22,99.5 ; 129 cut-outs
GND on BOTTOM: 86.03,97.41 85.85,97.48 85.78,97.66 85.78,99.28 85.81,99.41 85.89,99.5 91.45,99.5 91.54,99.41 91.57,99.28 91.57,97.66 91.49,97.48 91.31,97.41
GND on BOTTOM: 48.44,99.28 48.44,76.07 47.83,75.46 45.26,75.46 41.1,71.29 31.52,71.29 30.45,70.23 30.45,59.51 29.36,58.42 23.24,58.42 21.31,56.49 21.31,39.54 21.01,39.24 0.5,39.24 0.5,98 0.94,99.06 2,99.5 48.22,99.5 ; 9 cut-outs
GND on BOTTOM: 134.24,68.63 134.31,68.45 134.49,68.37 135.76,68.37 135.94,68.45 136.02,68.63 136.02,70.79 135.94,70.97 135.76,71.04 134.49,71.04 134.31,70.97 134.24,70.79
GND on BOTTOM: 0.5,39.44 21.34,39.44 21.52,39.37 21.59,39.19 21.59,5.5 2,5.5 0.94,5.94 0.5,7 ; 2 cut-outs
GND on BOTTOM: 28.04,75.22 28.04,77.33 28.24,77.53 29.46,77.53 29.67,77.33 29.67,76.18 29.26,75.78 29.26,75.04 28.22,75.04
GND on GND02: 156,99.5 157.06,99.06 157.5,98 157.5,7 157.06,5.94 156,5.5 2,5.5 0.94,5.94 0.5,7 0.5,98 0.94,99.06 2,99.5 ; 5 cut-outs
GND on GND02: 61.65,97.25 61.47,97.33 61.39,97.51 61.39,99.41 61.4,99.46 61.41,99.5 98.13,99.5 98.14,99.46 98.15,99.41 98.15,97.51 98.07,97.33 97.89,97.25
GND on ART03: 156,99.5 157.06,99.06 157.5,98 157.5,7 157.06,5.94 156,5.5 2,5.5 0.94,5.94 0.5,7 0.5,98 0.94,99.06 2,99.5 ; 33 cut-outs
GND on ART03: 32.31,70.74 32.31,73.96 32.64,73.96 32.64,76.83 32.31,76.83 32.31,80.69 38.1,80.69 38.1,70.74
GND on ART04: 12.8,78.36 12.8,39.62 58.09,39.62 58.09,37.41 59.08,36.42 109.37,36.42 109.8,36.85 109.8,61.34 109.45,61.69 97.89,61.69 97.89,59.94 96.65,58.7 96.65,43.79 96.77,43.66 96.77,42.72 95.89,41.83 60.58,41.83 59.18,43.23 59.18,78.36 58.5,78.36 56.95,79.9 56.95,94.18 56.16,94.97 50.06,94.97 49.86,94.76 49.86,78.36
GND on ART04: 156,99.5 157.06,99.06 157.5,98 157.5,7 157.06,5.94 156,5.5 2,5.5 0.94,5.94 0.5,7 0.5,87.24 5.12,87.24 5.12,14.23 137.55,14.23 140.22,16.9 140.22,25.57 141.36,26.71 153.27,26.71 156.13,29.57 156.13,89.81 147.93,98 47.86,98 46.24,96.38 46.24,89.33 45.38,88.47 0.5,88.47 0.5,98 0.94,99.06 2,99.5 ; 5 cut-outs
GND on ART04: 0.5,85.77 0.5,89.38 5,89.38 5,85.77
VCC5V0_SYS on TOP: 2.77,59.15 15.29,59.15 15.75,59.61 15.75,69.13 16,69.39 16,71.34 14.71,71.34 14.71,69.39 14.07,68.75 14.07,62 13.61,61.54 6.86,61.54 6.86,60.73 6.68,60.55 2.77,60.55
